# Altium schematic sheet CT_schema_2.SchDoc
size 271 x 273 mm
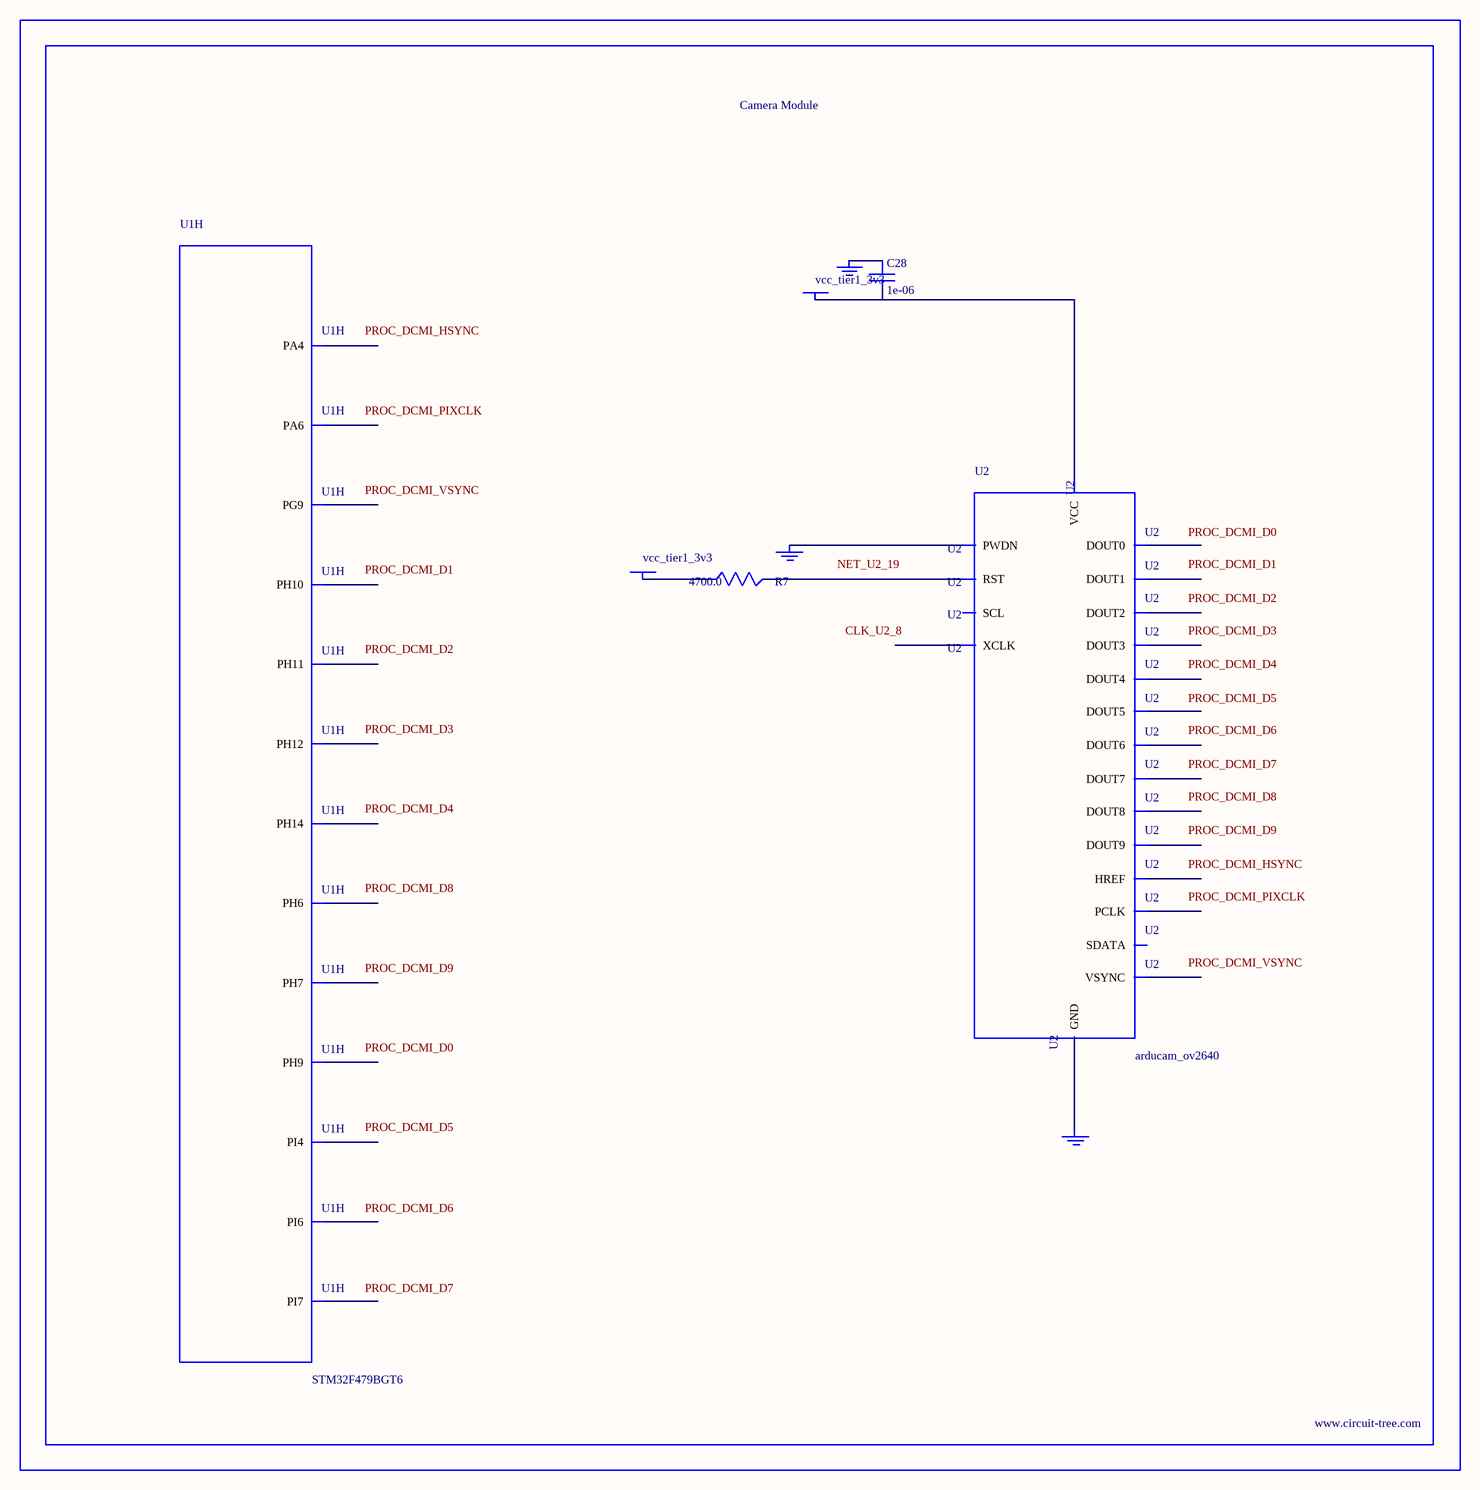
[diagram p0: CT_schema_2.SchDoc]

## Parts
BORDER1  (no value)
C28  1e-06  [C0603]
GND_INSTANCE_1_0  (no value)
GND_INSTANCE_1_1  (no value)
GND_INSTANCE_1_2  (no value)
POWER_INSTANCE_1_0  vcc_tier1_3v3
POWER_INSTANCE_1_1  vcc_tier1_3v3
R7  4700.0  [R0603]
U1  STM32F479BGT6  [LQFP208]  (part H of 16)
U2  arducam_ov2640  [ARDUCAM]

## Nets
NetC28_1: C28.1 GND_INSTANCE_1_0.0(GND)
NetC28_2: C28.2 POWER_INSTANCE_1_0.0(PWR) U2.1(VCC)
NetGND_INSTANCE_1_1_0: GND_INSTANCE_1_1.0(GND) U2.20(PWDN)
NetGND_INSTANCE_1_2_0: GND_INSTANCE_1_2.0(GND) U2.2(GND)
NetPOWER_INSTANCE_1_1_0: POWER_INSTANCE_1_1.0(PWR) R7.1
NetR7_2: R7.2 U2.19(RST)

Not connected (* = marked no-connect by the designer): U1 53(PA4) 55(PA6) 96(PH6) 97(PH7) 99(PH9) 100(PH10) 101(PH11) 102(PH12) 152(PH14) 178(PG9) 205(PI4) 207(PI6) 208(PI7); U2 3(SCL) 4(SDATA) 5(VSYNC) 6(HREF) 7(PCLK) 8(XCLK) 9(DOUT9) 10(DOUT8) 11(DOUT7) 12(DOUT6) 13(DOUT5) 14(DOUT4) 15(DOUT3) 16(DOUT2) 17(DOUT1) 18(DOUT0)

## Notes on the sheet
- Labels drawn without touching a wire or pin: CLK_U2_8, NET_U2_19, PROC_DCMI_D0, PROC_DCMI_D1, PROC_DCMI_D2, PROC_DCMI_D3, PROC_DCMI_D4, PROC_DCMI_D5, PROC_DCMI_D6, PROC_DCMI_D7, PROC_DCMI_D8, PROC_DCMI_D9, PROC_DCMI_HSYNC, PROC_DCMI_PIXCLK, PROC_DCMI_VSYNC

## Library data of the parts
BORDER1 = BORDER_PAGE1
C28 = C0603C105K3RACTU
GND_INSTANCE_1_0-GND_INSTANCE_1_2 = GND
POWER_INSTANCE_1_0 POWER_INSTANCE_1_1 = PWR
R7 = RC0603JR-074K7L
